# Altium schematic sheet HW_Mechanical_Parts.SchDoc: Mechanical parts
size A4; Date: Not used; ApprovedBy: Not used; CheckedBy: Not used; Author: Not used; CompanyName: STMicroelectronics; DrawnBy: Not used; Engineer: Not used; Organization: Not used; Address1: Not used; Address2: Not used; Address3: Not used; Address4: Not used; DocumentNumber: Not used; Revision: Not used; SheetNumber: 8; SheetTotal: 8
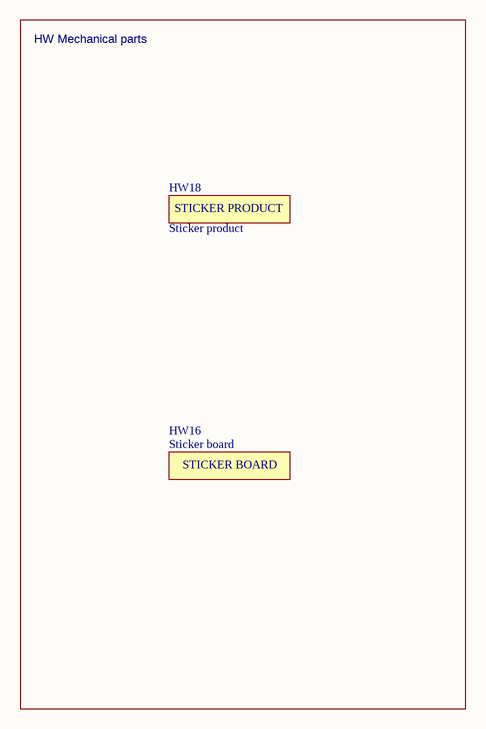
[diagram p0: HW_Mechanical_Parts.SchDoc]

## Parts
HW16  value Sticker board  [STICKER_BOARD_25X9]  (hidden comment: STICKER_BOARD)  (no BOM)
HW18  value Sticker product  [STICKER_PRODUCT_25X9]  (hidden comment: STICKER_PRODUCT)  (no BOM)

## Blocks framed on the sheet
HW Mechanical parts: HW16 HW18

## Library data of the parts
HW16 = MCD-00235: Sticker Board 25x9 mm; Part_Type: Misc; Part_Preference: Recommended
HW18 = MCD-00547: Sticker product 25x9 mm; Part_Type: Misc; Part_Preference: Recommended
